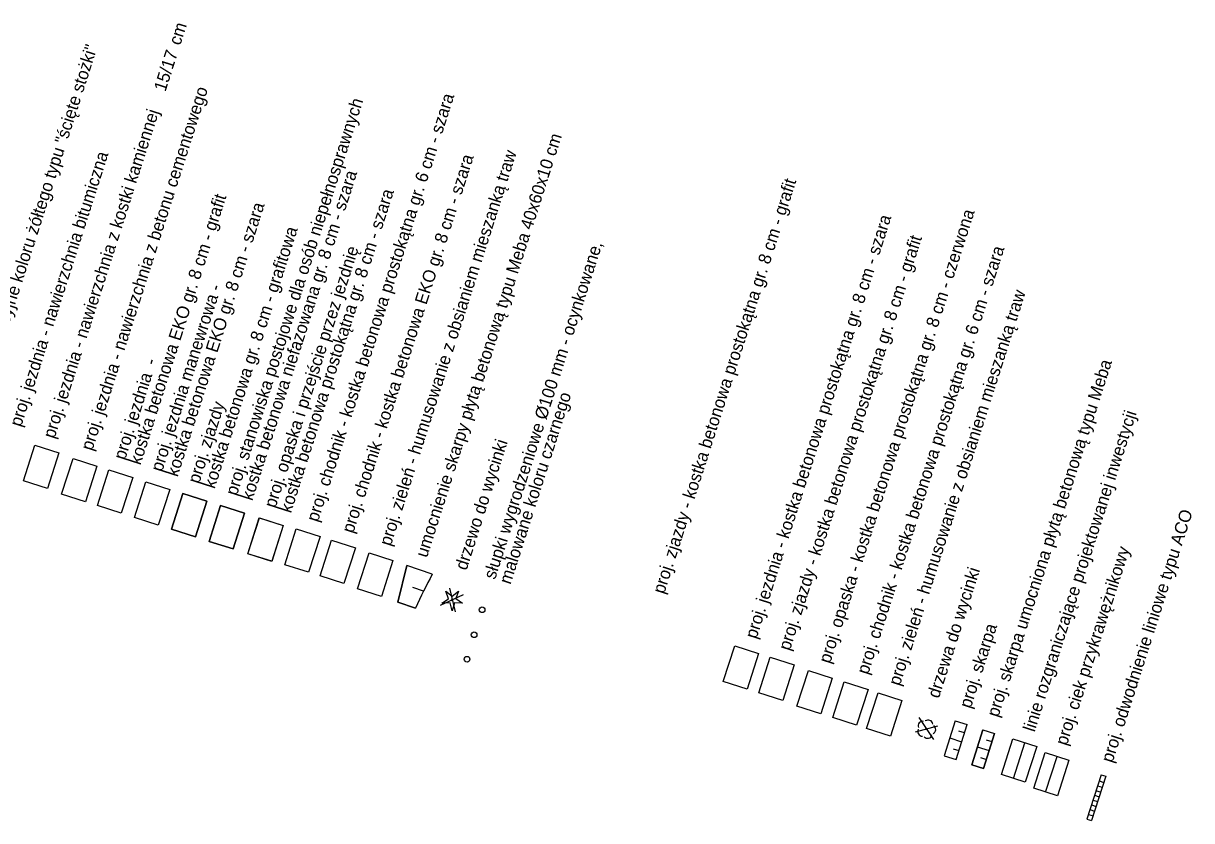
# Model space of a CAD drawing. Extents: x 6526191 to 6550417, y 6005093 to 6049233.
# Drawn here: x 6526852.2 to 6526945.5, y 6049154.8 to 6049218.5 of the extents above; entities that cross this region are included whole.
import ezdxf

# ---------------------------------------------------------------- set-up
doc = ezdxf.new("R2010")
doc.units = 0
for name, color, linetype in [('Default', 7, 'Continuous'), ('DRAFT_ciek', 7, 'Continuous'), ('DRAFT_kraweznik wystajacy', 7, 'Continuous'), ('DRAFT_linie rozgraniczające', 7, 'Continuous'), ('DRAFT_obrzeze', 7, 'Continuous'), ('DRAFT_odwodnienie liniowe', 7, 'Continuous'), ('DRAFT_opis', 7, 'Continuous'), ('DRAFT_skarpy', 7, 'Continuous'), ('DRAFT_wycinka', 7, 'Continuous'), ('fill chodnik', 7, 'Continuous'), ('fill jezdnia manewrowa', 7, 'Continuous'), ('fill jezdnia plac', 7, 'Continuous'), ('fill zieleń utwardzona', 7, 'Continuous'), ('fill zjazdy', 7, 'Continuous'), ('ROSLINNOSC', 7, 'Continuous')]:
    doc.layers.add(name, color=color, linetype=linetype)

# ---------------------------------------------------------------- blocks, each defined once
blk = doc.blocks.new('1422')
at = {"layer": 'ROSLINNOSC'}
blk.add_circle((0, 0), 0.1, dxfattribs=at)
for centre, start, end in [((-0.71, 0.23), 102.5, 221.75), ((0, 0.75), 30.19, 149.77), ((0.71, 0.23), 318.3, 77.49), ((-0.44, -0.61), 174.33, 293.45), ((0.44, -0.61), 246.24, 5.74)]:
    blk.add_arc(centre, 0.75, start, end, dxfattribs=at)
blk = doc.blocks.new('OBOP01_01')
at = {"layer": 'Default'}
blk.add_lwpolyline([(0, -1.74), (-0.35, -0.48), (-1.65, -0.54), (-0.57, 0.18), (-1.02, 1.4), (0, 0.6), (1.02, 1.4), (0.57, 0.18), (1.65, -0.54), (0.35, -0.48), (0, -1.74)], dxfattribs=at)
blk.add_circle((0, 0), 0.1, dxfattribs=at)
for start, end in [(90, 270), (270, 90)]:
    blk.add_arc((0, 0), 0.1, start, end, dxfattribs=at)

msp = doc.modelspace()

# ---------------------------------------------------------------- linework, layer by layer
at = {"layer": 'Default'}
for points in [[(6526930.301, 6049158.449), (6526931.215, 6049161.307), (6526933.12, 6049160.698), (6526932.206, 6049157.84)], [(6526932.877, 6049157.356), (6526933.79, 6049160.214), (6526935.695, 6049159.605), (6526934.782, 6049156.748)]]:
    msp.add_lwpolyline(points, close=True, dxfattribs=at)
at = {"layer": 'DRAFT_ciek'}
msp.add_line((6526933.829, 6049157.052), (6526934.743, 6049159.91), dxfattribs=at)
at = {"layer": 'DRAFT_kraweznik wystajacy'}
msp.add_lwpolyline([(6526868.925, 6049176.483), (6526869.838, 6049179.34), (6526867.933, 6049179.949), (6526867.02, 6049177.092), (6526868.925, 6049176.483)], dxfattribs=at)
at = {"layer": 'DRAFT_linie rozgraniczające'}
msp.add_line((6526931.254, 6049158.145), (6526932.167, 6049161.002), dxfattribs=at)
at = {"layer": 'DRAFT_obrzeze'}
for points in [[(6526853.104, 6049184.779), (6526855.009, 6049184.17), (6526854.095, 6049181.313), (6526852.19, 6049181.922)], [(6526873.972, 6049178.083), (6526875.877, 6049177.474), (6526874.963, 6049174.617), (6526873.058, 6049175.226)], [(6526875.88, 6049174.324), (6526876.794, 6049177.181), (6526878.699, 6049176.572), (6526877.785, 6049173.715)], [(6526879.789, 6049176.16), (6526881.694, 6049175.551), (6526880.78, 6049172.694), (6526878.875, 6049173.302)], [(6526911.84, 6049167.835), (6526913.745, 6049167.226), (6526912.832, 6049164.369), (6526910.927, 6049164.978)], [(6526914.883, 6049166.772), (6526916.788, 6049166.164), (6526915.875, 6049163.306), (6526913.97, 6049163.915)], [(6526920.45, 6049164.993), (6526922.355, 6049164.384), (6526921.442, 6049161.527), (6526919.537, 6049162.135)]]:
    msp.add_lwpolyline(points, close=True, dxfattribs=at)
at = {"layer": 'DRAFT_odwodnienie liniowe'}
for p, q in [((6526938.257, 6049158.441), (6526937.123, 6049154.894)), ((6526938.257, 6049158.441), (6526938.638, 6049158.319)), ((6526938.638, 6049158.321), (6526937.504, 6049154.772)), ((6526937.975, 6049157.561), (6526938.356, 6049157.439)), ((6526938.097, 6049157.942), (6526938.478, 6049157.82)), ((6526937.732, 6049156.799), (6526938.113, 6049156.677)), ((6526937.854, 6049157.18), (6526938.235, 6049157.058)), ((6526937.366, 6049155.656), (6526937.747, 6049155.534)), ((6526937.488, 6049156.037), (6526937.869, 6049155.915)), ((6526937.61, 6049156.418), (6526937.991, 6049156.296)), ((6526937.123, 6049154.894), (6526937.504, 6049154.772)), ((6526937.245, 6049155.275), (6526937.626, 6049155.153)), ((6526937.245, 6049155.275), (6526937.626, 6049155.153))]:
    msp.add_line(p, q, dxfattribs=at)
at = {"layer": 'DRAFT_opis'}
for p, q in [((6526882.806, 6049175.168), (6526882.085, 6049172.243)), ((6526884.839, 6049174.469), (6526882.806, 6049175.168)), ((6526886.685, 6049171.462), (6526886.246, 6049173.354)), ((6526885.51, 6049171.979), (6526887.347, 6049172.848)), ((6526882.085, 6049172.243), (6526883.497, 6049171.758))]:
    msp.add_line(p, q, dxfattribs=at)
for centre in [(6526888.822, 6049171.62), (6526888.184, 6049169.626), (6526887.617, 6049167.671)]:
    msp.add_circle(centre, 0.225, dxfattribs=at)
msp.add_arc((6526936.715, 6049147.106), 58.65, 152.18911, 155.14463, dxfattribs=at)
at = {"layer": 'DRAFT_skarpy'}
for p, q in [((6526882.085, 6049172.243), (6526882.806, 6049175.168)), ((6526884.839, 6049174.469), (6526882.806, 6049175.168)), ((6526884.15, 6049173.12), (6526883.293, 6049173.414)), ((6526883.497, 6049171.758), (6526882.085, 6049172.243)), ((6526926.61, 6049162.74), (6526925.729, 6049159.945)), ((6526926.61, 6049162.74), (6526927.556, 6049162.445)), ((6526926.675, 6049159.65), (6526927.556, 6049162.445)), ((6526926.175, 6049161.377), (6526927.12, 6049161.083)), ((6526926.883, 6049161.942), (6526927.328, 6049161.803)), ((6526928.811, 6049162.036), (6526927.93, 6049159.241)), ((6526928.811, 6049162.036), (6526929.757, 6049161.742)), ((6526928.876, 6049158.947), (6526929.757, 6049161.742)), ((6526929.084, 6049161.239), (6526929.529, 6049161.1)), ((6526926.437, 6049160.51), (6526926.898, 6049160.367)), ((6526928.376, 6049160.674), (6526929.321, 6049160.379)), ((6526925.729, 6049159.945), (6526926.675, 6049159.65)), ((6526928.638, 6049159.806), (6526929.098, 6049159.663)), ((6526927.93, 6049159.241), (6526928.876, 6049158.947))]:
    msp.add_line(p, q, dxfattribs=at)
msp.add_arc((6526936.715, 6049147.106), 58.65, 152.18911, 155.14463, dxfattribs=at)
at = {"layer": 'DRAFT_wycinka'}
for p, q in [((6526923.448, 6049161.858), (6526925.231, 6049162.345)), ((6526923.706, 6049163.004), (6526924.874, 6049161.258))]:
    msp.add_line(p, q, dxfattribs=at)
at = {"layer": 'fill chodnik'}
for points in [[(6526861.053, 6049178.999), (6526861.967, 6049181.856), (6526863.872, 6049181.247), (6526862.958, 6049178.39)], [(6526861.053, 6049178.999), (6526861.967, 6049181.856), (6526863.872, 6049181.247), (6526862.958, 6049178.39)], [(6526864.016, 6049178.052), (6526864.929, 6049180.909), (6526866.834, 6049180.3), (6526865.921, 6049177.443)], [(6526867.02, 6049177.092), (6526867.933, 6049179.949), (6526869.838, 6049179.34), (6526868.925, 6049176.483)], [(6526870.12, 6049176.101), (6526871.033, 6049178.958), (6526872.938, 6049178.35), (6526872.025, 6049175.492)], [(6526916.827, 6049163.002), (6526917.741, 6049165.859), (6526919.646, 6049165.25), (6526918.733, 6049162.393)], [(6526916.827, 6049163.002), (6526917.741, 6049165.859), (6526919.646, 6049165.25), (6526918.733, 6049162.393)]]:
    msp.add_lwpolyline(points, close=True, dxfattribs=at)
msp.add_lwpolyline([(6526865.921, 6049177.443), (6526866.834, 6049180.3), (6526864.929, 6049180.909), (6526864.016, 6049178.052), (6526865.921, 6049177.443)], dxfattribs=at)
at = {"layer": 'fill jezdnia manewrowa'}
for points in [[(6526858.091, 6049179.945), (6526859.004, 6049182.803), (6526860.909, 6049182.194), (6526859.996, 6049179.337)], [(6526858.091, 6049179.945), (6526859.004, 6049182.803), (6526860.909, 6049182.194), (6526859.996, 6049179.337)], [(6526908.998, 6049168.744), (6526910.903, 6049168.135), (6526909.99, 6049165.277), (6526908.085, 6049165.886)], [(6526908.085, 6049165.886), (6526908.998, 6049168.744), (6526910.903, 6049168.135), (6526909.99, 6049165.277)]]:
    msp.add_lwpolyline(points, close=True, dxfattribs=at)
at = {"layer": 'fill jezdnia plac'}
for points in [[(6526852.19, 6049181.922), (6526853.104, 6049184.779), (6526855.009, 6049184.17), (6526854.095, 6049181.313)], [(6526873.058, 6049175.226), (6526873.972, 6049178.083), (6526875.877, 6049177.474), (6526874.963, 6049174.617)], [(6526875.88, 6049174.324), (6526876.794, 6049177.181), (6526878.699, 6049176.572), (6526877.785, 6049173.715)], [(6526878.875, 6049173.302), (6526879.789, 6049176.16), (6526881.694, 6049175.551), (6526880.78, 6049172.694)], [(6526910.927, 6049164.978), (6526911.84, 6049167.835), (6526913.745, 6049167.226), (6526912.832, 6049164.369)], [(6526913.97, 6049163.915), (6526914.883, 6049166.772), (6526916.788, 6049166.164), (6526915.875, 6049163.306)], [(6526919.537, 6049162.135), (6526920.45, 6049164.993), (6526922.355, 6049164.384), (6526921.442, 6049161.527)]]:
    msp.add_lwpolyline(points, close=True, dxfattribs=at)
at = {"layer": 'fill zieleń utwardzona'}
msp.add_lwpolyline([(6526927.93, 6049159.241), (6526928.811, 6049162.036), (6526929.757, 6049161.742), (6526928.876, 6049158.947)], close=True, dxfattribs=at)
at = {"layer": 'fill zjazdy'}
for points in [[(6526855.233, 6049180.859), (6526856.146, 6049183.716), (6526858.051, 6049183.108), (6526857.138, 6049180.25)], [(6526855.233, 6049180.859), (6526856.146, 6049183.716), (6526858.051, 6049183.108), (6526857.138, 6049180.25)], [(6526870.111, 6049176.103), (6526871.025, 6049178.961), (6526872.93, 6049178.352), (6526872.017, 6049175.495)]]:
    msp.add_lwpolyline(points, close=True, dxfattribs=at)

# ---------------------------------------------------------------- block references
at = {"layer": 'ROSLINNOSC', "yscale": 0.4999999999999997}
for name, p, xscale, rotation in [('OBOP01_01', (6526886.43, 6049172.419), 0.49999999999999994, 72.27537868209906), ('1422', (6526924.305, 6049162.094), 0.4999999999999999, 49.47166007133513)]:
    msp.add_blockref(name, p, dxfattribs=dict(at, xscale=xscale, rotation=rotation))

# ---------------------------------------------------------------- texts
at = {"layer": 'Default'}
for s, p in [('cm', (6526864.706, 6049216.67)), ('płytki integracyjne koloru żółtego typu "ścięte stożki" ', (6526848.724, 6049187.229)), ('15/17 ', (6526863.524, 6049212.972)), ('proj. jezdnia - nawierzchnia z betonu cementowego', (6526857.68, 6049184.276)), ('proj. chodnik - kostka betonowa prostokątna gr. 6 cm - szara', (6526875.705, 6049178.579)), ('proj. jezdnia - nawierzchnia z kostki kamiennej ', (6526854.661, 6049185.241)), ('proj. stanowiska postojowe dla osób niepełnosprawnych', (6526869.226, 6049180.676)), ('umocnienie skarpy płytą betonową typu Meba 40x60x10 cm', (6526884.414, 6049175.732)), ('proj. jezdnia - nawierzchnia bitumiczna', (6526851.994, 6049186.184)), ('proj. chodnik - kostka betonowa EKO gr. 8 cm - szara', (6526878.527, 6049177.677)), ('proj. zieleń - humusowanie z obsianiem mieszanką traw', (6526881.522, 6049176.656)), ('kostka betonowa niefazowana gr. 8 cm - szara', (6526870.459, 6049180.282)), ('proj. zjazdy - kostka betonowa prostokątna gr. 8 cm - grafit', (6526903.358, 6049172.827)), ('kostka betonowa prostokątna gr. 8 cm - szara', (6526873.55, 6049179.294)), ('kostka betonowa EKO gr. 8 cm - grafit', (6526861.53, 6049183.136)), ('kostka betonowa EKO gr. 8 cm - szara', (6526864.492, 6049182.189)), ('proj. opaska - kostka betonowa prostokątna gr. 8 cm - czerwona', (6526916.616, 6049167.268)), ('proj. jezdnia - kostka betonowa prostokątna gr. 8 cm - szara', (6526910.731, 6049169.24)), ('kostka betonowa gr. 8 cm - grafitowa', (6526867.455, 6049181.242)), ('proj. zjazdy - kostka betonowa prostokątna gr. 8 cm - grafit', (6526913.398, 6049168.297)), ('proj. opaska i przejście przez jezdnię', (6526872.318, 6049179.688)), ('słupki wygrodzeniowe Ø100 mm - ocynkowane, ', (6526889.857, 6049173.992)), ('proj. chodnik - kostka betonowa prostokątna gr. 6 cm - szara', (6526919.65, 6049166.389)), ('proj. jezdnia manewrowa - ', (6526863.259, 6049182.583)), ('proj. zieleń - humusowanie z obsianiem mieszanką traw', (6526922.184, 6049165.489)), ('proj. jezdnia  - ', (6526860.297, 6049183.53)), ('proj. skarpa umocniona płytą betonową typu Meba', (6526930.048, 6049162.976)), ('proj. zjazdy', (6526866.222, 6049181.636)), ('malowane koloru czarnego', (6526891.09, 6049173.598)), ('linie rozgraniczające projektowanej inwestycji', (6526932.948, 6049161.803)), ('drzewo do wycinki', (6526887.575, 6049174.721)), ('proj. odwodnienie liniowe typu ACO', (6526939.17, 6049159.341)), ('proj. ciek przykrawężnikowy', (6526935.523, 6049160.71)), ('drzewa do wycinki', (6526925.304, 6049164.492)), ('proj. skarpa', (6526927.847, 6049163.679))]:
    msp.add_text(s, height=1, rotation=72.27538, dxfattribs=at).set_placement(p)

doc.saveas('drawing.dxf')
